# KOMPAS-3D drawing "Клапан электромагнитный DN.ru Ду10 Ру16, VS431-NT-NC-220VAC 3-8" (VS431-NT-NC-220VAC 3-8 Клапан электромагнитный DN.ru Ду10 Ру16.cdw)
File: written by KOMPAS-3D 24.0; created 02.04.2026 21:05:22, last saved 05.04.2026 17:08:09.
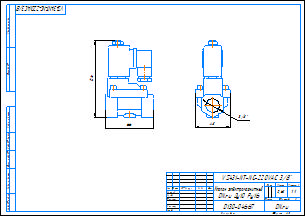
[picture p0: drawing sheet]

Document properties: c3d_UniqueCompID: ef56311e-7521-43dc-8291-0e6108b3d81d; Обозначение: VS400-ET-NC-220VAC 3-8; Наименование: Клапан электромагнитный DN.ru Ду10 Ру16; Автор: artio; Класс точности: c; Знак неуказанной шероховатости: Шероховатость не задана; Рассекать на разрезах: Да; Автор: artio; Форматы листов документа: A3; Полное имя файла: VS431-NT-NC-220VAC 3-8 Клапан электромагнитный DN.ru Ду10 Ру16.m3d; Масса: 0.62; Наименование: Клапан электромагнитный DN.ru Ду10 Ру16; Количество листов документа: 1; Примечание: D130-04667

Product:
- Body: Тело 1  | qty 1
    Масса: 1.030062
- Part/product: Клапан электромагнитный DN.ru Ду10 Ру16  | designation VS431-NT-NC-220VAC 3-8
    Масса: 0.62
    Раздел спецификации: Прочие изделия
    Примечание: D130-04667
    additional columns: ef56311e-7521-43dc-8291-0e6108b3d81d; VS400-ET-NC-220VAC 3-8; artio; c; Шероховатость не задана; Да

Views: Вид 1, Спереди, Проекционный вид 2
Referenced files in C:\Users\artio\OneDrive\Рабочий стол\Клапан электромагнитный DN.ru VS4x-xT-NC-x\DN10\: VS400-ET-NC-220VAC 3-8 Клапан электромагнитный DN.ru Ду10 Ру16.m3d
Referenced files in C:\Users\artio\OneDrive\Рабочий стол\Клапан электромагнитный DN.ru\VS431\VS431-NT-NC\VS431-NT-NC-220VAC\Ду10\: VS431-NT-NC-220VAC 3-8 Клапан электромагнитный DN.ru Ду10 Ру16.m3d
Referenced files in C:\Users\artio\OneDrive\Рабочий стол\Клапан электромагнитный DN.ru\VS400-NT-NC\VS400-NT-NC-220VAC\: VS400-NT-NC-220VAC 3-8 Клапан электромагнитный DN.ru Ду10 Ру16.cdw
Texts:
  VS431-NT-NC-220VAC 3-8
  Линейный размер
  Клапан электромагнитный
  DN.ru Ду10 Ру16
  VS431-NT-NC-220VAC 3/8"
  VS431-NT-NC-220VAC 3/8"-
  Клапан электромагнитный DN.ru Ду10 Ру16
  VS431-NT-NC-220VAC 3-8 Клапан электромагнитный DN.ru Ду10 Ру16
Dimensions and other numbers on the sheet: 0; 3; 2; 4; 48; 3/8"; 66; 106; 1:1; 1; 0,62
